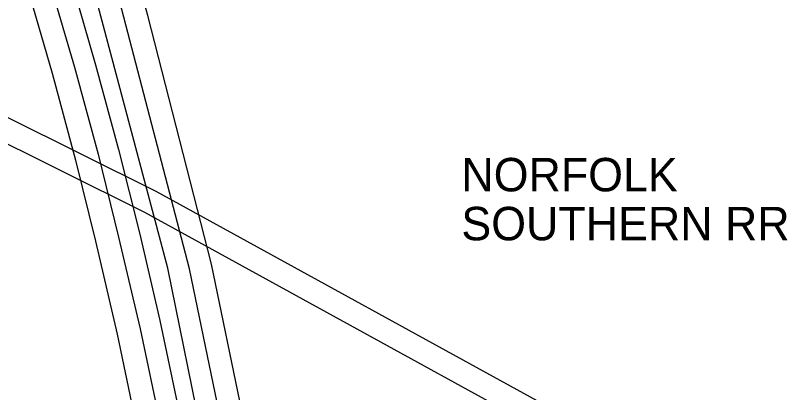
# Model space of a CAD drawing. Extents: x 1855721 to 1876784, y 662259 to 674089.
# Drawn here: x 1876126.6 to 1876541.8, y 668039.1 to 668242.1 of the extents above; entities that cross this region are included whole.
import ezdxf

# ---------------------------------------------------------------- set-up
doc = ezdxf.new("R2010")
doc.units = 0
for name, color, linetype in [('GE_X_Alignment_100_Bearings', 7, 'Continuous'), ('GE_X_Alignment_100_Curve_Data', 7, 'Continuous'), ('RD_X_RR_1', 7, 'Continuous'), ('SC_Scratch1', 7, 'Continuous')]:
    doc.layers.add(name, color=color, linetype=linetype)

msp = doc.modelspace()

# ---------------------------------------------------------------- linework, layer by layer
at = {"layer": 'GE_X_Alignment_100_Bearings'}
for points in [[(1876342.22, 667030.85), (1876320.95, 667279.53), (1876295.48, 667572), (1876286.18, 667671.69), (1876276.12, 667768.79), (1876263.19, 667868.83), (1876245.97, 667976.92), (1876241.59, 668002.57), (1876220.16, 668105.69), (1876181.66, 668253.69), (1876177.13, 668269.38), (1876168.9, 668295.66)], [(1876145.51, 668258.33), (1876158.33, 668214.27), (1876171.11, 668167.32), (1876182.05, 668122.69), (1876193.68, 668073.47), (1876204.61, 668021.39), (1876209.5, 667994.05), (1876228.72, 667876.2), (1876242.63, 667770.23), (1876252.58, 667669), (1876261.19, 667572.06), (1876283.85, 667315.88), (1876308.95, 667031.23)]]:
    msp.add_lwpolyline(points, dxfattribs=at)
at = {"layer": 'GE_X_Alignment_100_Curve_Data'}
for p, q in [((1876197.74, 668242.07), (1876192.53, 668261.45)), ((1876133.69, 668254.44), (1876146.41, 668210.91)), ((1876231.97, 668108.27), (1876197.74, 668242.07)), ((1876146.41, 668210.91), (1876158.92, 668164.25)), ((1876158.92, 668164.25), (1876169.69, 668120.6)), ((1876169.69, 668120.6), (1876181.3, 668070.49)), ((1876255.31, 667995.6), (1876231.97, 668108.27)), ((1876181.3, 668070.49), (1876189.94, 668028.95))]:
    msp.add_line(p, q, dxfattribs=at)
for points in [[(1876149.57, 668283.91), (1876156.73, 668260.56), (1876169.73, 668215.55), (1876181.99, 668169.89), (1876193.59, 668124.32), (1876204.27, 668077.83), (1876217.35, 668015.58)], [(1876228.17, 668009.85), (1876208.52, 668106.09), (1876165.79, 668267.46), (1876162.96, 668276.88)]]:
    msp.add_lwpolyline(points, dxfattribs=at)
at = {"layer": 'RD_X_RR_1'}
for points in [[(1875840.43, 668327.84), (1876202.17, 668147.44), (1876519.55, 667972.87)], [(1876513.34, 667961.58), (1876196.19, 668136.02), (1875834.68, 668316.3)]]:
    msp.add_lwpolyline(points, dxfattribs=at)

# ---------------------------------------------------------------- texts
at = {"layer": 'SC_Scratch1'}
for s, p in [('NORFOLK', (1876366.4, 668147.38)), ('SOUTHERN RR', (1876366.4, 668121.05))]:
    msp.add_text(s, height=18, dxfattribs=at).set_placement(p)

doc.saveas('drawing.dxf')
